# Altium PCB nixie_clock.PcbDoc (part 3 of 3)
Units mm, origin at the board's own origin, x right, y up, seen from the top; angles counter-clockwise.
Board outline 295 x 120 mm, 2 copper layers (Top Layer, Bottom Layer), stack 0.325 mm thick; 320 components, 396 nets, 1330 pads, 452 vias.
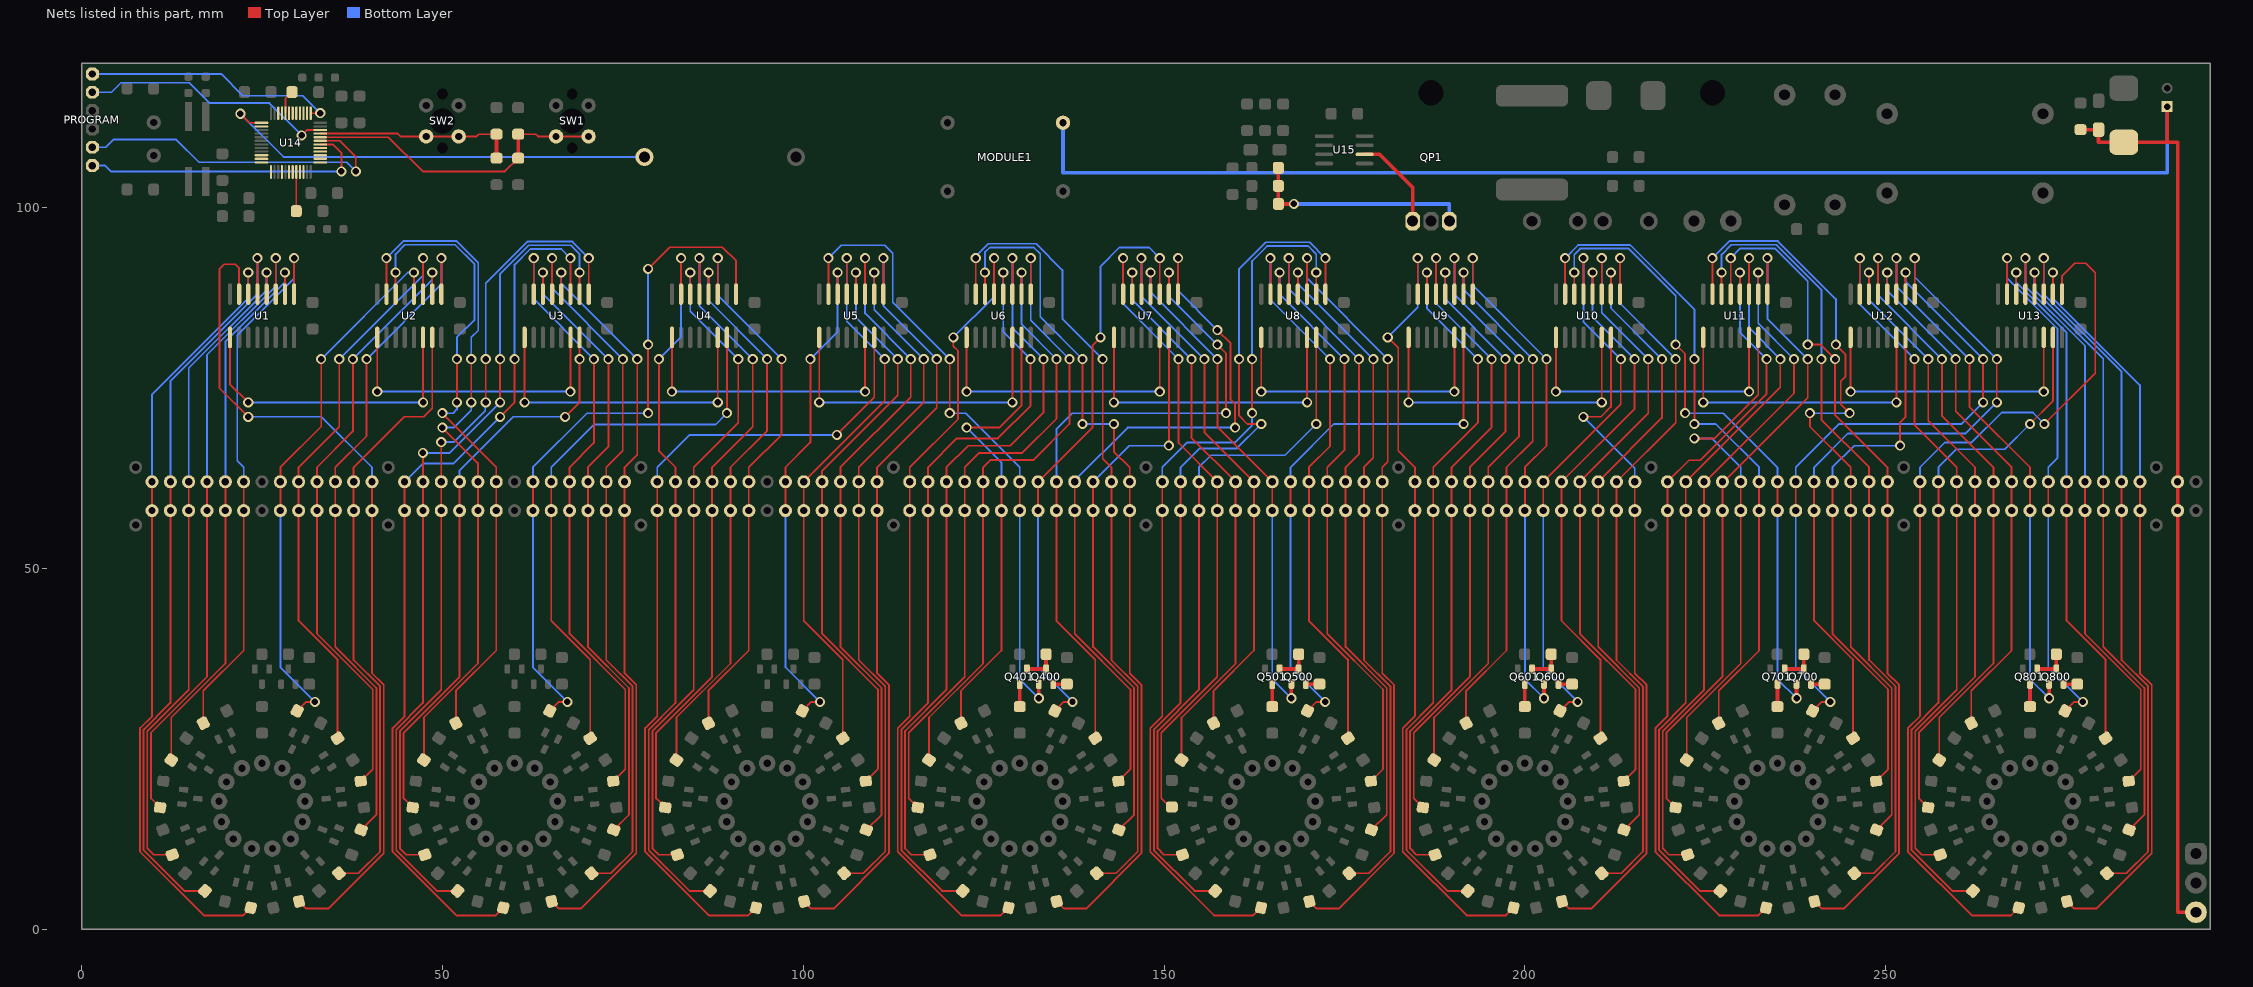
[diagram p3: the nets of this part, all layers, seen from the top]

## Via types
v1: diameter 1.397, hole 0.889, Top Layer to Bottom Layer, 452 vias

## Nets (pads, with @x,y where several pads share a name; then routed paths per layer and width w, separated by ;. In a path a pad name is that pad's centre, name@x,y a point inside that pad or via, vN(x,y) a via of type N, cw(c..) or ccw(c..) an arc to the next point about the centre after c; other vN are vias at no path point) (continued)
NetQ400_1: pad.400 Q400.1 U5.7 | length 88.4
  Top Layer w0.254: U5.7@103.492,88 v1(103.492,93) ; v1(120.3,71.5) v1(120.3,79) ; pad.400@130,58 pad.400@130,62
  Top Layer w0.508: v1(132.65,32) Q400.1@132.65,33.95
  Bottom Layer w0.254: v1(103.492,93) 105.262,94.77 111.31,94.77 112.4,93.68 112.4,86.9 v1(120.3,79) ; v1(120.3,71.5) 122.5,71.5 130,64 pad.400@130,62 ; pad.400@130,58 130,34.65 v1(132.65,32)
NetQ400_2: Q400.2 R400.1 | length 1.9
  Top Layer w0.508: Q400.2@134.65,33.95 R400.1@136.55,33.954
NetQ400_3: Q400.3 Q401.1 R402.2 | length 4.7
  Top Layer w0.508: Q401.1@131,36.05 Q400.3@133.65,36.05 R402.2@133.652,38.1
NetQ401_3: Q401.3 R401.1 | length 3.1
  Top Layer w0.508: R401.1@130,30.842 Q401.3@130,33.95
NetQ500_1: pad.500 Q500.1 U7.4 | length 72
  Top Layer w0.254: U7.4@148.135,88 v1(148.135,91) ; v1(157.4,79) 157.4,69.6 pad.500@165,62 pad.500@165,58
  Top Layer w0.508: v1(167.65,32) Q500.1@167.65,33.95
  Bottom Layer w0.254: v1(148.135,91) 148.135,88.265 v1(157.4,79) ; pad.500@165,58 165,34.65 v1(167.65,32)
NetQ500_2: Q500.2 R500.1 | length 1.9
  Top Layer w0.508: Q500.2@169.65,33.95 R500.1@171.55,33.954
NetQ500_3: Q500.3 Q501.1 R502.2 | length 4.7
  Top Layer w0.508: Q501.1@166,36.05 Q500.3@168.65,36.05 R502.2@168.651,38.1
NetQ501_3: Q501.3 R501.1 | length 3.1
  Top Layer w0.508: R501.1@165,30.842 Q501.3@165,33.95
NetQ600_1: pad.600 Q600.1 U9.1 | length 74.5
  Top Layer w0.254: U9.1@192.778,88 v1(192.778,93) ; pad.600@200,58 pad.600@200,62 200,64 203,67 v1(203,79)
  Top Layer w0.508: v1(202.65,32) Q600.1@202.65,33.95
  Bottom Layer w0.254: v1(192.778,93) 192.778,89.222 v1(203,79) ; pad.600@200,58 200,34.65 v1(202.65,32)
NetQ600_2: Q600.2 R600.1 | length 1.9
  Top Layer w0.508: Q600.2@204.65,33.95 R600.1@206.55,33.954
NetQ600_3: Q600.3 Q601.1 R602.2 | length 4.7
  Top Layer w0.508: Q601.1@201,36.05 Q600.3@203.65,36.05 R602.2@203.652,38.1
NetQ601_3: Q601.3 R601.1 | length 3.1
  Top Layer w0.508: R601.1@200,30.842 Q601.3@200,33.95
NetQ700_1: pad.700 Q700.1 U10.6 | length 90.4
  Top Layer w0.254: U10.6@206.845,88 v1(206.845,91) ; v1(220.9,81) 222.2,79.7 v1(222.2,71.5) ; pad.700@235,58 pad.700@235,62
  Top Layer w0.508: v1(237.65,32) Q700.1@237.65,33.95
  Bottom Layer w0.254: v1(206.845,91) 206.845,93.485 207.66,94.3 214.382,94.3 220.9,87.782 v1(220.9,81) ; v1(222.2,71.5) 227.5,71.5 235,64 pad.700@235,62 ; pad.700@235,58 235,34.65 v1(237.65,32)
NetQ700_2: Q700.2 R700.1 | length 1.9
  Top Layer w0.508: Q700.2@239.65,33.95 R700.1@241.55,33.954
NetQ700_3: Q700.3 Q701.1 R702.2 | length 4.7
  Top Layer w0.508: Q701.1@236,36.05 Q700.3@238.65,36.05 R702.2@238.651,38.1
NetQ701_3: Q701.3 R701.1 | length 3.1
  Top Layer w0.508: R701.1@235,30.842 Q701.3@235,33.95
NetQ800_1: pad.800 Q800.1 U12.3 | length 76.7
  Top Layer w0.254: U12.3@251.488,88 v1(251.488,93) ; v1(261.6,79) 261.6,72.4 270,64 pad.800@270,62 pad.800@270,58
  Top Layer w0.508: v1(272.65,32) Q800.1@272.65,33.95
  Bottom Layer w0.254: v1(251.488,93) 251.488,89.112 v1(261.6,79) ; pad.800@270,58 270,34.65 v1(272.65,32)
NetQ800_2: Q800.2 R800.1 | length 1.9
  Top Layer w0.508: Q800.2@274.65,33.95 R800.1@276.55,33.954
NetQ800_3: Q800.3 Q801.1 R802.2 | length 4.7
  Top Layer w0.508: Q801.1@271,36.05 Q800.3@273.65,36.05 R802.2@273.651,38.1
NetQ801_3: Q801.3 R801.1 | length 3.1
  Top Layer w0.508: R801.1@270,30.842 Q801.3@270,33.95
NetQP1_1: QP1.1 U15.6 | length 14.2
  Top Layer w0.508: U15.6@177.8,107.365 179.885,107.365 184.46,102.79 QP1.1@184.46,98.11 QP1.1@184.46,97.11
NetQP1_3: QP1.3 RP8.2 RP10.1 RP11.1 | length 31.1
  Top Layer w0.508: RP8.2@165.842,105.5 RP10.1@165.842,103 RP11.1@165.842,100.5 v1(168,100.5)
  Bottom Layer w0.508: v1(168,100.5) 189.54,100.5 QP1.3@189.54,98.11
NetR1_2: pad.1 R1.2 U1.1 | length 75.4
  Top Layer w0.254: R1.2@16.863,28.541 16.863,33.022 22.46,38.618 pad.1@22.46,58 pad.1@22.46,62 ; U1.1@29.445,88 v1(29.445,93)
  Bottom Layer w0.254: pad.1@22.46,62 22.46,64 21.56,64.9 21.56,82.33 29.445,90.215 v1(29.445,93)
NetR2_2: pad.2 R2.2 U1.2 | length 77.1
  Top Layer w0.254: R2.2@12.432,23.438 12.432,29.327 19.92,36.815 pad.2@19.92,58 pad.2@19.92,62 ; U1.2@28.175,88 v1(28.175,91)
  Bottom Layer w0.254: pad.2@19.92,62 19.92,81.408 28.175,89.663 v1(28.175,91)
NetR3_2: pad.3 R3.2 U1.3 | length 88.8
  Top Layer w0.254: R3.2@10.88,16.86 9.614,18.126 9.614,27.227 17.38,34.993 pad.3@17.38,58 pad.3@17.38,62 ; U1.3@26.905,88 v1(26.905,93)
  Bottom Layer w0.254: pad.3@17.38,62 17.38,79.587 26.905,89.112 v1(26.905,93)
NetR4_2: pad.4 R4.2 U1.4 | length 93.5
  Top Layer w0.254: R4.2@12.563,10.314 9.976,10.314 9.106,11.184 9.106,27.438 14.84,33.172 pad.4@14.84,58 pad.4@14.84,62 ; U1.4@25.635,88 v1(25.635,91)
  Bottom Layer w0.254: pad.4@14.84,62 14.84,77.765 25.635,88.56 v1(25.635,91)
NetR5_2: pad.5 R5.2 U1.5 | length 104.4
  Top Layer w0.254: pad.5@12.3,62 pad.5@12.3,58 12.3,31.35 8.598,27.648 8.598,10.94 14.239,5.3 R5.2@17.094,5.3 ; U1.5@24.365,88 v1(24.365,93)
  Bottom Layer w0.254: pad.5@12.3,62 12.3,75.944 24.365,88.009 v1(24.365,93)
NetR6_2: pad.6 R6.2 U1.6 | length 108.9
  Top Layer w0.254: pad.6@9.76,62 pad.6@9.76,58 9.76,29.528 8.09,27.858 8.09,10.73 16.92,1.9 22.371,1.9 R6.2@23.437,2.966 ; U1.6@23.095,88 v1(23.095,91)
  Bottom Layer w0.254: pad.6@9.769,62 9.769,74.131 23.095,87.457 v1(23.095,91)
NetR7_2: pad.7 R7.2 U1.7 | length 118.4
  Top Layer w0.254: U1.7@21.825,88 21.825,91.575 21.27,92.13 19.79,92.13 19.1,91.44 19.1,74.995 v1(23.095,71) ; R7.2@30.138,3.847 31.135,2.85 34.2,2.85 41.87,10.52 41.87,33.844 40.24,35.474 pad.7@40.24,58 pad.7@40.24,62
  Bottom Layer w0.254: v1(23.095,71) 33.24,71 40.24,64 pad.7@40.24,62
NetR8_2: pad.8 R8.2 U2.15 | length 85.8
  Top Layer w0.254: R8.2@35.662,7.742 38.342,7.742 41.362,10.762 41.362,33.633 37.7,37.295 pad.8@37.7,58 pad.8@37.7,62 37.7,64 44.7,71 47.402,71 48.592,72.19 U2.15@48.592,82
NetR9_2: pad.9 R9.2 U2.1 | length 93.6
  Top Layer w0.254: R9.2@38.743,13.757 40.854,15.868 40.854,33.423 35.16,39.117 pad.9@35.16,58 pad.9@35.16,62 35.16,64 39.5,68.34 v1(39.5,79) ; U2.1@49.862,88 v1(49.862,93)
  Bottom Layer w0.254: v1(39.5,79) 49.862,89.362 v1(49.862,93)
NetR10_2: pad.10 R10.2 U2.2 | length 84
  Top Layer w0.254: v1(37.6,79) 37.6,68.98 32.62,64 pad.10@32.62,62 pad.10@32.62,58 32.62,40.938 40.346,33.212 40.346,22.185 R10.2@38.676,20.515 ; U2.2@48.592,88 v1(48.592,91)
  Bottom Layer w0.254: v1(37.6,79) 48.592,89.992 v1(48.592,91)
NetR11_2: pad.11 R11.2 U2.3 | length 80.9
  Top Layer w0.254: R11.2@35.476,26.468 35.476,37.364 30.08,42.76 pad.11@30.08,58 pad.11@30.08,62 30.08,64 35.7,69.62 v1(35.7,79) ; U2.3@47.322,88 v1(47.322,93)
  Bottom Layer w0.254: v1(35.7,79) 47.322,90.622 v1(47.322,93)
NetR12_2: pad.12 R12.2 U2.4 | length 75.6
  Top Layer w0.254: pad.12@27.54,58 pad.12@27.54,62 27.54,64 33.2,69.66 v1(33.2,79) ; R12.2@29.876,30.252 31.125,31.5 v1(32.32,31.5) ; U2.4@46.052,88 v1(46.052,91)
  Bottom Layer w0.254: pad.12@27.54,58 27.54,36.28 v1(32.32,31.5) ; v1(33.2,79) 45.2,91 v1(46.052,91)
NetR13_2: pad.13 R13.2 U2.6 | length 89.8
  Top Layer w0.254: U2.6@43.512,88 v1(43.512,91) ; v1(50,71.5) 57.46,64.04 pad.13@57.46,62 pad.13@57.46,58 57.46,38.618 51.863,33.022 R13.2@51.863,28.541 ; v1(52,73) v1(52,79)
  Bottom Layer w0.254: v1(43.512,91) 43.512,93.552 44.792,94.832 51.746,94.832 54.452,92.126 54.452,84.452 52,82 v1(52,79) ; v1(50,71.5) 51.48,71.5 52,72.02 v1(52,73)
NetR14_2: pad.14 R14.2 U2.7 | length 97
  Top Layer w0.254: U2.7@42.242,88 v1(42.242,93) ; R14.2@47.432,23.438 47.432,29.327 54.92,36.815 pad.14@54.92,58 pad.14@54.92,62 54.92,64.58 v1(50,69.5) ; v1(54,73) v1(54,79)
  Bottom Layer w0.254: v1(42.242,93) 44.582,95.34 51.957,95.34 54.96,92.337 54.96,82.96 54,82 v1(54,79) ; v1(50,69.5) 51.59,69.5 54,71.91 v1(54,73)
NetR15_2: pad.15 R15.2 U3.15 | length 80
  Top Layer w0.254: R15.2@45.88,16.86 44.614,18.126 44.614,27.227 52.38,34.993 pad.15@52.38,58 pad.15@52.38,62 ; v1(67,71) 69.008,73.008 v1(69.008,79) U3.15@69.008,82
  Bottom Layer w0.254: pad.15@52.38,62 52.38,63.58 59.8,71 v1(67,71)
NetR16_2: pad.16 R16.2 U3.1 | length 110.7
  Top Layer w0.254: R16.2@47.563,10.314 44.976,10.314 44.106,11.184 44.106,27.438 49.84,33.172 pad.16@49.84,58 pad.16@49.84,62 v1(49.84,67.5) ; v1(56,73) v1(56,79) ; U3.1@70.278,88 v1(70.278,93)
  Bottom Layer w0.254: v1(49.84,67.5) 51.6,67.5 55.93,71.83 55.93,72.93 v1(56,73) ; v1(56,79) 56,89.52 61.75,95.27 68.008,95.27 v1(70.278,93)
NetR17_2: pad.17 R17.2 U3.2 | length 117.5
  Top Layer w0.254: v1(47.3,66) pad.17@47.3,62 pad.17@47.3,58 47.3,31.35 43.598,27.648 43.598,10.94 49.239,5.3 R17.2@52.094,5.3 ; v1(58,73) v1(58,79) ; U3.2@69.008,88 v1(69.008,91)
  Bottom Layer w0.254: v1(47.3,66) 51,66 v1(58,73) ; v1(58,79) 58,90.802 61.96,94.762 67.798,94.762 69.008,93.552 v1(69.008,91)
NetR18_2: pad.18 R18.2 U3.3 | length 124.4
  Top Layer w0.254: pad.18@44.76,62 pad.18@44.76,58 44.76,29.528 43.09,27.858 43.09,10.73 51.92,1.9 57.371,1.9 R18.2@58.437,2.966 ; v1(58,71) 60,73 v1(60,79) ; U3.3@67.738,88 v1(67.738,93)
  Bottom Layer w0.254: pad.18@44.76,62 47.28,64.52 51.52,64.52 v1(58,71) ; v1(60,79) 60,92.083 62.171,94.254 66.484,94.254 v1(67.738,93)
NetR19_2: pad.19 R19.2 U3.4 | length 104.6
  Top Layer w0.254: R19.2@65.138,3.847 66.135,2.85 69.2,2.85 76.87,10.52 76.87,33.844 75.24,35.474 pad.19@75.24,58 pad.19@75.24,62 75.24,64 77,65.76 v1(77,79) ; U3.4@66.468,88 v1(66.468,91)
  Bottom Layer w0.254: v1(66.468,91) 66.468,89.532 v1(77,79)
NetR20_2: pad.20 R20.2 U3.5 | length 100.7
  Top Layer w0.254: U3.5@65.198,88 v1(65.198,93) ; R20.2@70.662,7.742 73.342,7.742 76.362,10.762 76.362,33.633 72.7,37.295 pad.20@72.7,58 pad.20@72.7,62 72.7,64 75,66.3 v1(75,79)
  Bottom Layer w0.254: v1(65.198,93) 65.198,88.802 v1(75,79)
NetR21_2: pad.21 R21.2 U3.6 | length 88.4
  Top Layer w0.254: U3.6@63.928,88 v1(63.928,91) ; v1(73,79) 73,66.84 70.16,64 pad.21@70.16,62 pad.21@70.16,58 70.16,39.117 75.854,33.423 75.854,15.868 R21.2@73.743,13.757
  Bottom Layer w0.254: v1(63.928,91) 63.928,88.072 v1(73,79)
NetR22_2: pad.22 R22.2 U3.7 | length 86.2
  Top Layer w0.254: U3.7@62.658,88 v1(62.658,93) ; v1(71,79) 71,67.38 67.62,64 pad.22@67.62,62 pad.22@67.62,58 67.62,40.938 75.346,33.212 75.346,22.185 R22.2@73.676,20.515
  Bottom Layer w0.254: v1(62.658,93) 62.658,87.342 v1(71,79)
NetR23_2: pad.23 R23.2 U4.15 | length 77.7
  Top Layer w0.254: pad.23@65.08,62 pad.23@65.08,58 65.08,42.76 70.476,37.364 R23.2@70.476,26.468 ; v1(89.425,71.5) U4.15@89.425,82
  Bottom Layer w0.254: pad.23@65.08,62 65.08,64 71.001,69.921 87.846,69.921 v1(89.425,71.5)
NetR24_2: pad.24 R24.2 U4.1 | length 95.3
  Top Layer w0.254: pad.24@62.54,58 pad.24@62.54,62 ; R24.2@64.876,30.252 66.125,31.5 v1(67.32,31.5) ; v1(78.5,71.5) v1(78.5,81) ; v1(78.5,91.5) 81.5,94.5 88.8,94.5 90.695,92.605 U4.1@90.695,88
  Bottom Layer w0.254: pad.24@62.54,58 62.54,36.28 v1(67.32,31.5) ; pad.24@62.54,62 62.54,64 70.04,71.5 v1(78.5,71.5) ; v1(78.5,81) v1(78.5,91.5)
NetR25_2: pad.25 R25.2 U4.3 | length 77.3
  Top Layer w0.254: R25.2@86.863,28.541 86.863,33.022 92.46,38.618 pad.25@92.46,58 pad.25@92.46,62 92.46,64 97,68.54 v1(97,79) ; U4.3@88.155,88 v1(88.155,93)
  Bottom Layer w0.254: v1(88.155,93) 88.155,87.845 v1(97,79)
NetR26_2: pad.26 R26.2 U4.4 | length 79.1
  Top Layer w0.254: R26.2@82.432,23.438 82.432,29.327 89.92,36.815 pad.26@89.92,58 pad.26@89.92,62 89.92,64 95,69.08 v1(95,79) ; U4.4@86.885,88 v1(86.885,91)
  Bottom Layer w0.254: v1(86.885,91) 86.885,87.115 v1(95,79)
NetR27_2: pad.27 R27.2 U4.5 | length 90.3
  Top Layer w0.254: R27.2@80.88,16.86 79.614,18.126 79.614,27.227 87.38,34.993 pad.27@87.38,58 pad.27@87.38,62 87.38,64 93,69.62 v1(93,79) ; U4.5@85.615,88 v1(85.615,93)
  Bottom Layer w0.254: v1(85.615,93) 85.615,86.385 v1(93,79)
NetR28_2: pad.28 R28.2 U4.6 | length 94.3
  Top Layer w0.254: R28.2@82.563,10.314 79.976,10.314 79.106,11.184 79.106,27.438 84.84,33.172 pad.28@84.84,58 pad.28@84.84,62 84.84,64 91,70.16 v1(91,79) ; U4.6@84.345,88 v1(84.345,91)
  Bottom Layer w0.254: v1(84.345,91) 84.345,85.655 v1(91,79)
NetR29_2: pad.29 R29.2 U4.7 | length 101.7
  Top Layer w0.254: v1(80,79) 80,66.3 82.3,64 pad.29@82.3,62 pad.29@82.3,58 82.3,31.35 78.598,27.648 78.598,10.94 84.239,5.3 R29.2@87.094,5.3 ; U4.7@83.075,88 v1(83.075,93)
  Bottom Layer w0.254: v1(80,79) 83.075,82.075 v1(83.075,93)
NetR30_2: pad.30 R30.2 U5.15 | length 115.8
  Top Layer w0.254: pad.30@79.76,62 pad.30@79.76,58 79.76,29.528 78.09,27.858 78.09,10.73 86.92,1.9 92.371,1.9 R30.2@93.437,2.966 ; v1(104.66,68.5) 109.842,73.682 U5.15@109.842,82
  Bottom Layer w0.254: pad.30@79.76,62 79.76,64 84.26,68.5 v1(104.66,68.5)
NetR31_2: pad.31 R31.2 U5.1 | length 110
  Top Layer w0.254: R31.2@100.138,3.847 101.135,2.85 104.2,2.85 111.87,10.52 111.87,33.844 110.24,35.474 pad.31@110.24,58 pad.31@110.24,62 110.24,64 118.5,72.26 v1(118.5,79) ; U5.1@111.112,88 v1(111.112,93)
  Bottom Layer w0.254: v1(111.112,93) 111.112,86.388 v1(118.5,79)
NetR32_2: pad.32 R32.2 U5.2 | length 98.3
  Top Layer w0.254: R32.2@105.662,7.742 108.342,7.742 111.362,10.762 111.362,33.633 107.7,37.295 pad.32@107.7,58 pad.32@107.7,62 107.7,64 116.7,73 v1(116.7,79) ; U5.2@109.842,88 v1(109.842,91)
  Bottom Layer w0.254: v1(109.842,91) 109.842,85.858 v1(116.7,79)
NetR33_2: pad.33 R33.2 U5.3 | length 94.1
  Top Layer w0.254: U5.3@108.572,88 v1(108.572,93) ; R33.2@108.743,13.757 110.854,15.868 110.854,33.423 105.16,39.117 pad.33@105.16,58 pad.33@105.16,62 105.16,64 114.9,73.74 v1(114.9,79)
  Bottom Layer w0.254: v1(108.572,93) 108.572,85.328 v1(114.9,79)
NetR34_2: pad.34 R34.2 U5.4 | length 84.1
  Top Layer w0.254: U5.4@107.302,88 v1(107.302,91) ; R34.2@108.676,20.515 110.346,22.185 110.346,33.212 102.62,40.938 pad.34@102.62,58 pad.34@102.62,62 102.62,63.5 113.1,73.98 v1(113.1,79)
  Bottom Layer w0.254: v1(107.302,91) 107.302,84.798 v1(113.1,79)
NetR35_2: pad.35 R35.2 U5.5 | length 80.6
  Top Layer w0.254: R35.2@105.476,26.468 105.476,37.364 100.08,42.76 pad.35@100.08,58 pad.35@100.08,62 111.3,73.22 v1(111.3,79) ; U5.5@106.032,88 v1(106.032,93)
  Bottom Layer w0.254: v1(106.032,93) 106.032,84.268 v1(111.3,79)
NetR36_2: pad.36 R36.2 U5.6 | length 70.4
  Top Layer w0.254: pad.36@97.54,58 pad.36@97.54,62 97.54,64 101,67.46 v1(101,79) ; R36.2@99.876,30.252 101.125,31.5 v1(102.32,31.5) ; U5.6@104.762,88 v1(104.762,91)
  Bottom Layer w0.254: pad.36@97.54,58 97.54,36.28 v1(102.32,31.5) ; v1(101,79) 104.762,82.762 v1(104.762,91)
NetR37_2: pad.37 R37.2 U6.15 | length 63.6
  Top Layer w0.254: R37.2@121.863,28.541 121.863,33.022 127.46,38.618 pad.37@127.46,58 pad.37@127.46,62 ; v1(122.638,69.5) 127.17,69.5 130.258,72.588 U6.15@130.258,82
  Bottom Layer w0.254: v1(122.638,69.5) 127.46,64.678 pad.37@127.46,62
NetR38_2: pad.38 R38.2 U6.1 | length 88.3
  Top Layer w0.254: R38.2@117.432,23.438 117.432,29.327 124.92,36.815 pad.38@124.92,58 pad.38@124.92,62 124.92,64 125.92,65 131.88,65 136.9,70.02 v1(136.9,79) ; U6.1@131.528,88 v1(131.528,93)
  Bottom Layer w0.254: v1(131.528,93) 131.528,84.372 v1(136.9,79)
NetR39_2: pad.39 R39.2 U6.2 | length 91.7
  Top Layer w0.254: R39.2@115.88,16.86 114.614,18.126 114.614,27.227 122.38,34.993 pad.39@122.38,58 pad.39@122.38,62 122.38,64 124.38,66 130.35,66 135.1,70.75 v1(135.1,79) ; U6.2@130.258,88 v1(130.258,91)
  Bottom Layer w0.254: v1(130.258,91) 130.258,83.842 v1(135.1,79)
NetR40_2: pad.40 R40.2 U6.3 | length 103.8
  Top Layer w0.254: R40.2@117.563,10.314 114.976,10.314 114.106,11.184 114.106,27.438 119.84,33.172 pad.40@119.84,58 pad.40@119.84,62 119.84,64 122.84,67 128.69,67 133.3,71.61 v1(133.3,79) ; U6.3@128.988,88 v1(128.988,93)
  Bottom Layer w0.254: v1(128.988,93) 128.988,83.312 v1(133.3,79)
NetR41_2: pad.41 R41.2 U6.4 | length 106.2
  Top Layer w0.254: R41.2@122.094,5.3 119.239,5.3 113.598,10.94 113.598,27.648 117.3,31.35 pad.41@117.3,58 pad.41@117.3,62 117.3,64 121.3,68 126.98,68 131.5,72.52 v1(131.5,79) ; U6.4@127.718,88 v1(127.718,91)
  Bottom Layer w0.254: v1(127.718,91) 127.718,82.782 v1(131.5,79)
NetR42_2: pad.42 R42.2 U6.5 | length 112.8
  Top Layer w0.254: v1(120.8,82) 120.8,80.79 121.45,80.14 121.45,70.69 114.76,64 pad.42@114.76,62 pad.42@114.76,58 114.76,29.528 113.09,27.858 113.09,10.73 121.92,1.9 127.371,1.9 R42.2@128.437,2.966 ; U6.5@126.448,88 v1(126.448,93)
  Bottom Layer w0.254: v1(120.8,82) 126.448,87.648 v1(126.448,93)
NetR43_2: pad.43 R43.2 U6.6 | length 120.8
  Top Layer w0.254: U6.6@125.178,88 v1(125.178,91) ; R43.2@135.138,3.847 136.135,2.85 139.2,2.85 146.87,10.52 146.87,33.844 145.24,35.474 pad.43@145.24,58 pad.43@145.24,62 145.24,64 143.055,66.185 v1(143.055,70) ; v1(138.7,70) v1(138.7,79)
  Bottom Layer w0.254: v1(125.178,91) 125.178,93.788 125.852,94.462 131.968,94.462 132.84,93.59 132.84,84.86 v1(138.7,79) ; v1(138.7,70) v1(143.055,70)
NetR44_2: pad.44 R44.2 U6.7 | length 111.3
  Top Layer w0.254: U6.7@123.908,88 v1(123.908,93) ; R44.2@140.662,7.742 143.342,7.742 146.362,10.762 146.362,33.633 142.7,37.295 pad.44@142.7,58 pad.44@142.7,62 142.7,64 141.5,65.2 v1(141.5,79)
  Bottom Layer w0.254: v1(123.908,93) 123.908,93.237 125.642,94.97 132.27,94.97 135.91,91.33 135.91,84.59 v1(141.5,79)
NetR45_2: pad.45 R45.2 U7.15 | length 79.1
  Top Layer w0.254: pad.45@140.16,62 pad.45@140.16,58 140.16,39.117 145.854,33.423 145.854,15.868 R45.2@143.743,13.757 ; v1(150.675,67) 150.675,70.515 U7.15@150.675,82
  Bottom Layer w0.254: pad.45@140.16,62 145.16,67 v1(150.675,67)
NetR46_2: pad.46 R46.2 U7.1 | length 102.6
  Top Layer w0.254: pad.46@137.62,62 pad.46@137.62,58 137.62,40.938 145.346,33.212 145.346,22.185 R46.2@143.676,20.515 ; U7.1@151.945,88 v1(151.945,93) ; v1(157.4,83) 159.22,81.18 159.22,73.39 159.84,72.77 v1(159.84,69.5)
  Bottom Layer w0.254: pad.46@137.62,62 137.62,62.178 144.942,69.5 v1(159.84,69.5) ; v1(151.945,93) 151.945,88.455 v1(157.4,83)
NetR47_2: pad.47 R47.2 U7.2 | length 95.3
  Top Layer w0.254: pad.47@135.08,62 pad.47@135.08,58 135.08,42.76 140.476,37.364 R47.2@140.476,26.468 ; U7.2@150.675,88 v1(150.675,91) ; v1(157.4,81) 158.59,79.81 v1(158.59,71.5)
  Bottom Layer w0.254: pad.47@135.08,62 135.08,69.29 137.29,71.5 v1(158.59,71.5) ; v1(150.675,91) 150.675,87.725 v1(157.4,81)
NetR48_2: pad.48 R48.2 U7.3 | length 83.8
  Top Layer w0.254: pad.48@132.54,58 pad.48@132.54,62 140.1,69.56 140.1,80.9 v1(141.2,82) ; R48.2@134.876,30.252 136.125,31.5 v1(137.32,31.5) ; U7.3@149.405,88 v1(149.405,93)
  Bottom Layer w0.254: pad.48@132.54,58 132.54,36.28 v1(137.32,31.5) ; v1(141.2,82) 141.2,91.84 143.82,94.46 147.945,94.46 v1(149.405,93)
NetR49_2: pad.49 R49.2 U7.5 | length 78.2
  Top Layer w0.254: U7.5@146.865,88 v1(146.865,93) ; v1(155.6,79) 155.6,68.86 pad.49@162.46,62 pad.49@162.46,58 162.46,38.618 156.863,33.022 R49.2@156.863,28.541
  Bottom Layer w0.254: v1(146.865,93) 146.865,87.735 v1(155.6,79)
NetR50_2: pad.50 R50.2 U7.6 | length 79.6
  Top Layer w0.254: U7.6@145.595,88 v1(145.595,91) ; R50.2@152.432,23.438 152.432,29.327 159.92,36.815 pad.50@159.92,58 pad.50@159.92,62 153.8,68.12 v1(153.8,79)
  Bottom Layer w0.254: v1(145.595,91) 145.595,87.205 v1(153.8,79)
NetR51_2: pad.51 R51.2 U7.7 | length 90.3
  Top Layer w0.254: U7.7@144.325,88 v1(144.325,93) ; R51.2@150.88,16.86 149.614,18.126 149.614,27.227 157.38,34.993 pad.51@157.38,58 pad.51@157.38,62 152,67.38 v1(152,79)
  Bottom Layer w0.254: v1(144.325,93) 144.325,86.675 v1(152,79)
NetR52_2: pad.52 R52.2 U8.15 | length 89.7
  Top Layer w0.254: R52.2@152.563,10.314 149.976,10.314 149.106,11.184 149.106,27.438 154.84,33.172 pad.52@154.84,58 pad.52@154.84,62 ; v1(171.092,70) U8.15@171.092,82
  Bottom Layer w0.254: pad.52@154.84,62 154.84,64 156.51,65.67 166.762,65.67 v1(171.092,70)
NetR53_2: pad.53 R53.2 U8.1 | length 122.4
  Top Layer w0.254: pad.53@152.3,62 pad.53@152.3,58 152.3,31.35 148.598,27.648 148.598,10.94 154.239,5.3 R53.2@157.094,5.3 ; v1(160.4,79) 160.4,71.16 161.56,70 v1(163.472,70) ; U8.1@172.362,88 v1(172.362,93)
  Bottom Layer w0.254: pad.53@152.3,62 152.3,64 154.93,66.63 160.102,66.63 v1(163.472,70) ; v1(160.4,79) 160.4,91.51 164.07,95.18 170.182,95.18 v1(172.362,93)
NetR54_2: pad.54 R54.2 U8.2 | length 127.4
  Top Layer w0.254: pad.54@149.76,62 pad.54@149.76,58 149.76,29.528 148.09,27.858 148.09,10.73 156.92,1.9 162.371,1.9 R54.2@163.437,2.966 ; v1(162.2,71.5) v1(162.2,79) ; U8.2@171.092,88 v1(171.092,91)
  Bottom Layer w0.254: pad.54@149.76,58 pad.54@149.76,58.62 ; pad.54@149.76,62 149.76,64 153.22,67.46 159.86,67.46 162.2,69.8 v1(162.2,71.5) ; v1(162.2,79) 162.2,92.592 164.28,94.672 169.968,94.672 171.092,93.548 v1(171.092,91)
NetR55_2: pad.55 R55.2 U8.3 | length 108.4
  Top Layer w0.254: U8.3@169.822,88 v1(169.822,93) ; R55.2@170.138,3.847 171.135,2.85 174.2,2.85 181.87,10.52 181.87,33.844 180.24,35.474 pad.55@180.24,58 pad.55@180.24,62 180.24,64 181,64.76 v1(181,79)
  Bottom Layer w0.254: v1(169.822,93) 169.822,90.178 v1(181,79)
NetR56_2: pad.56 R56.2 U8.4 | length 96.6
  Top Layer w0.254: U8.4@168.552,88 v1(168.552,91) ; R56.2@175.662,7.742 178.342,7.742 181.362,10.762 181.362,33.633 177.7,37.295 pad.56@177.7,58 pad.56@177.7,62 177.7,64 179,65.3 v1(179,79)
  Bottom Layer w0.254: v1(168.552,91) 168.552,89.448 v1(179,79)
NetR57_2: pad.57 R57.2 U8.5 | length 92.3
  Top Layer w0.254: U8.5@167.282,88 v1(167.282,93) ; v1(177,79) 177,65.84 175.16,64 pad.57@175.16,62 pad.57@175.16,58 175.16,39.117 180.854,33.423 180.854,15.868 R57.2@178.743,13.757
  Bottom Layer w0.254: v1(167.282,93) 167.282,88.718 v1(177,79)
NetR58_2: pad.58 R58.2 U8.6 | length 82.1
  Top Layer w0.254: U8.6@166.012,88 v1(166.012,91) ; v1(175,79) 175,66.38 172.62,64 pad.58@172.62,62 pad.58@172.62,58 172.62,40.938 180.346,33.212 180.346,22.185 R58.2@178.676,20.515
  Bottom Layer w0.254: v1(166.012,91) 166.012,87.988 v1(175,79)
NetR59_2: pad.59 R59.2 U8.7 | length 78.4
  Top Layer w0.254: U8.7@164.742,88 v1(164.742,93) ; v1(173,79) 173,66.92 170.08,64 pad.59@170.08,62 pad.59@170.08,58 170.08,42.76 175.476,37.364 R59.2@175.476,26.468
  Bottom Layer w0.254: v1(164.742,93) 164.742,87.258 v1(173,79)
NetR60_2: pad.60 R60.2 U9.15 | length 75.9
  Top Layer w0.254: pad.60@167.54,58 pad.60@167.54,62 ; R60.2@169.876,30.252 171.125,31.5 v1(172.32,31.5) ; v1(191.508,70) U9.15@191.508,82
  Bottom Layer w0.254: pad.60@167.54,58 167.54,36.28 v1(172.32,31.5) ; pad.60@167.54,62 167.54,64 173.54,70 v1(191.508,70)
NetR61_2: pad.61 R61.2 U9.2 | length 73.3
  Top Layer w0.254: U9.2@191.508,88 v1(191.508,91) ; R61.2@191.863,28.541 191.863,33.022 197.46,38.618 pad.61@197.46,58 pad.61@197.46,62 197.46,64 201.1,67.64 v1(201.1,79)
  Bottom Layer w0.254: v1(191.508,91) 191.508,88.592 v1(201.1,79)
NetR62_2: pad.62 R62.2 U9.3 | length 83.1
  Top Layer w0.254: R62.2@187.432,23.438 187.432,29.327 194.92,36.815 pad.62@194.92,58 pad.62@194.92,62 194.92,64 199.2,68.28 v1(199.2,79) ; U9.3@190.238,88 v1(190.238,93)
  Bottom Layer w0.254: v1(190.238,93) 190.238,87.962 v1(199.2,79)
NetR63_2: pad.63 R63.2 U9.4 | length 86.4
  Top Layer w0.254: R63.2@185.88,16.86 184.614,18.126 184.614,27.227 192.38,34.993 pad.63@192.38,58 pad.63@192.38,62 192.38,64 197.3,68.92 v1(197.3,79) ; U9.4@188.968,88 v1(188.968,91)
  Bottom Layer w0.254: v1(188.968,91) 188.968,87.332 v1(197.3,79)
NetR64_2: pad.64 R64.2 U9.5 | length 98.5
  Top Layer w0.254: R64.2@187.563,10.314 184.976,10.314 184.106,11.184 184.106,27.438 189.84,33.172 pad.64@189.84,58 pad.64@189.84,62 189.84,64 195.4,69.56 v1(195.4,79) ; U9.5@187.698,88 v1(187.698,93)
  Bottom Layer w0.254: v1(187.698,93) 187.698,86.702 v1(195.4,79)
NetR65_2: pad.65 R65.2 U9.6 | length 100.9
  Top Layer w0.254: U9.6@186.428,88 v1(186.428,91) ; R65.2@192.094,5.3 189.239,5.3 183.598,10.94 183.598,27.648 187.3,31.35 pad.65@187.3,58 pad.65@187.3,62 187.3,64 193.5,70.2 v1(193.5,79)
  Bottom Layer w0.254: v1(186.428,91) 186.428,86.072 v1(193.5,79)
NetR66_2: pad.66 R66.2 U9.7 | length 110.7
  Top Layer w0.254: v1(181,82) 182.46,80.54 182.46,66.3 184.76,64 pad.66@184.76,62 pad.66@184.76,58 184.76,29.528 183.09,27.858 183.09,10.73 191.92,1.9 197.371,1.9 R66.2@198.437,2.966 ; U9.7@185.158,88 v1(185.158,93)
  Bottom Layer w0.254: v1(181,82) 185.158,86.158 v1(185.158,93)
NetR67_2: pad.67 R67.2 U10.15 | length 93.4
  Top Layer w0.254: R67.2@205.138,3.847 206.135,2.85 209.2,2.85 216.87,10.52 216.87,33.844 215.24,35.474 pad.67@215.24,58 pad.67@215.24,62 ; v1(208.115,71) 210.55,71 211.925,72.375 U10.15@211.925,82
  Bottom Layer w0.254: v1(208.115,71) 215.24,63.875 pad.67@215.24,62
NetR68_2: pad.68 R68.2 U10.1 | length 102.3
  Top Layer w0.254: R68.2@210.662,7.742 213.342,7.742 216.362,10.762 216.362,33.633 212.7,37.295 pad.68@212.7,58 pad.68@212.7,62 220.9,70.2 v1(220.9,79) ; U10.1@213.195,88 v1(213.195,93)
  Bottom Layer w0.254: v1(213.195,93) 213.195,86.705 v1(220.9,79)
NetR69_2: pad.69 R69.2 U10.2 | length 90.1
  Top Layer w0.254: U10.2@211.925,88 v1(211.925,91) ; R69.2@213.743,13.757 215.854,15.868 215.854,33.423 210.16,39.117 pad.69@210.16,58 pad.69@210.16,62 219,70.84 v1(219,79)
  Bottom Layer w0.254: v1(211.925,91) 211.925,86.075 v1(219,79)
NetR70_2: pad.70 R70.2 U10.3 | length 88
  Top Layer w0.254: U10.3@210.655,88 v1(210.655,93) ; R70.2@213.676,20.515 215.346,22.185 215.346,33.212 207.62,40.938 pad.70@207.62,58 pad.70@207.62,62 217.1,71.48 v1(217.1,79)
  Bottom Layer w0.254: v1(210.655,93) 210.655,85.445 v1(217.1,79)
NetR71_2: pad.71 R71.2 U10.4 | length 76.4
  Top Layer w0.254: U10.4@209.385,88 v1(209.385,91) ; R71.2@210.476,26.468 210.476,37.364 205.08,42.76 pad.71@205.08,58 pad.71@205.08,62 215.2,72.12 v1(215.2,79)
  Bottom Layer w0.254: v1(209.385,91) 209.385,84.815 v1(215.2,79)
NetR72_2: pad.72 R72.2 U10.5 | length 78
  Top Layer w0.254: pad.72@202.54,58 pad.72@202.54,62 213.3,72.76 v1(213.3,79) ; R72.2@204.876,30.252 206.125,31.5 v1(207.32,31.5) ; U10.5@208.115,88 v1(208.115,93)
  Bottom Layer w0.254: pad.72@202.54,58 202.54,36.28 v1(207.32,31.5) ; v1(208.115,93) 208.115,84.185 v1(213.3,79)
NetR73_2: pad.73 R73.2 U10.7 | length 92.5
  Top Layer w0.254: U10.7@205.575,88 v1(205.575,93) ; v1(223.5,70) v1(223.5,79) ; R73.2@226.863,28.541 226.863,33.022 232.46,38.618 pad.73@232.46,58 pad.73@232.46,62
  Bottom Layer w0.254: v1(205.575,93) 207.383,94.808 214.592,94.808 223.5,85.9 v1(223.5,79) ; v1(223.5,70) 226.46,70 232.46,64 pad.73@232.46,62
NetR74_2: pad.74 R74.2 U11.15 | length 71
  Top Layer w0.254: R74.2@222.432,23.438 222.432,29.327 229.92,36.815 pad.74@229.92,58 pad.74@229.92,62 ; v1(223.5,68) 226.3,68 232.342,74.042 U11.15@232.342,82
  Bottom Layer w0.254: v1(223.5,68) 225.92,68 229.92,64 pad.74@229.92,62
NetR75_2: pad.75 R75.2 U11.1 | length 92.2
  Top Layer w0.254: R75.2@220.88,16.86 219.614,18.126 219.614,27.227 227.38,34.993 pad.75@227.38,58 pad.75@227.38,62 227.558,62 239.158,73.6 239.2,73.6 v1(239.2,79) ; U11.1@233.612,88 v1(233.612,93)
  Bottom Layer w0.254: v1(233.612,93) 233.612,84.588 v1(239.2,79)
NetR76_2: pad.76 R76.2 U11.2 | length 96.3
  Top Layer w0.254: R76.2@222.563,10.314 219.976,10.314 219.106,11.184 219.106,27.438 224.84,33.172 pad.76@224.84,58 pad.76@224.84,62 225.018,62 237.3,74.282 v1(237.3,79) ; U11.2@232.342,88 v1(232.342,91)
  Bottom Layer w0.254: v1(232.342,91) 232.342,83.958 v1(237.3,79)
NetR77_2: pad.77 R77.2 U11.3 | length 106.6
  Top Layer w0.254: R77.2@227.094,5.3 224.239,5.3 218.598,10.94 218.598,27.648 222.3,31.35 pad.77@222.3,58 pad.77@222.3,62 235.4,75.1 v1(235.4,79) ; U11.3@231.072,88 v1(231.072,93)
  Bottom Layer w0.254: v1(231.072,93) 231.072,83.328 v1(235.4,79)
NetR78_2: pad.78 R78.2 U11.4 | length 111.5
  Top Layer w0.254: U11.4@229.802,88 v1(229.802,91) ; R78.2@233.437,2.966 232.371,1.9 226.92,1.9 218.09,10.73 218.09,27.858 219.76,29.528 pad.78@219.76,58 pad.78@219.76,62 222.75,64.99 224.3,64.99 233.5,74.19 v1(233.5,79)
  Bottom Layer w0.254: v1(229.802,91) 229.802,82.698 v1(233.5,79)
NetR79_2: pad.79 R79.2 U11.5 | length 119
  Top Layer w0.254: U11.5@228.532,88 v1(228.532,93) ; v1(239.2,81) 241,81 v1(243,79) 243,71.24 250.24,64 pad.79@250.24,62 pad.79@250.24,58 250.24,35.474 251.87,33.844 251.87,10.52 244.2,2.85 241.135,2.85 R79.2@240.138,3.847
  Bottom Layer w0.254: v1(228.532,93) 229.872,94.34 234.643,94.34 239.2,89.783 v1(239.2,81)
NetR80_2: pad.80 R80.2 U11.6 | length 111.5
  Top Layer w0.254: U11.6@227.262,88 v1(227.262,91) ; v1(241.1,79) 241.1,70.6 247.7,64 pad.80@247.7,62 pad.80@247.7,58 247.7,37.295 251.362,33.633 251.362,10.762 248.342,7.742 R80.2@245.662,7.742
  Bottom Layer w0.254: v1(227.262,91) 227.262,93.482 228.628,94.848 234.854,94.848 241.1,88.602 v1(241.1,79)
NetR81_2: pad.81 R81.2 U11.7 | length 112.4
  Top Layer w0.254: U11.7@225.992,88 v1(225.992,93) ; v1(239.5,71.5) 239.5,69.66 245.16,64 pad.81@245.16,62 pad.81@245.16,58 245.16,39.117 250.854,33.423 250.854,15.868 R81.2@248.743,13.757 ; v1(243.1,81) 244.42,79.68 244.42,76.57 243.77,75.92 243.77,72.73 v1(245,71.5)
  Bottom Layer w0.254: v1(225.992,93) 228.348,95.356 235.064,95.356 243.1,87.32 v1(243.1,81) ; v1(239.5,71.5) v1(245,71.5)
NetR82_2: pad.82 R82.2 U12.15 | length 73.3
  Top Layer w0.254: pad.82@242.62,62 pad.82@242.62,58 242.62,40.938 250.346,33.212 250.346,22.185 R82.2@248.676,20.515 ; v1(252,67) 252,70.23 252.758,70.988 U12.15@252.758,82
  Bottom Layer w0.254: pad.82@242.62,62 242.62,64 245.62,67 v1(252,67)
NetR83_2: pad.83 R83.2 U12.1 | length 98.5
  Top Layer w0.254: pad.83@240.08,62 pad.83@240.08,58 240.08,42.76 245.476,37.364 R83.2@245.476,26.468 ; U12.1@254.028,88 v1(254.028,93) ; v1(265.4,73) v1(265.4,79)
  Bottom Layer w0.254: pad.83@240.08,62 240.08,64 244.78,68.7 261.1,68.7 v1(265.4,73) ; v1(254.028,93) 254.028,90.372 v1(265.4,79)
NetR84_2: pad.84 R84.2 U12.2 | length 92.6
  Top Layer w0.254: pad.84@237.54,58 pad.84@237.54,62 ; R84.2@239.876,30.252 241.125,31.5 v1(242.32,31.5) ; U12.2@252.758,88 v1(252.758,91) ; v1(263.5,73) v1(263.5,79)
  Bottom Layer w0.254: pad.84@237.54,58 237.54,36.28 v1(242.32,31.5) ; pad.84@237.54,62 237.54,64 243.565,70.025 260.525,70.025 v1(263.5,73) ; v1(252.758,91) 252.758,89.742 v1(263.5,79)
NetR85_2: pad.85 R85.2 U12.4 | length 74.9
  Top Layer w0.254: U12.4@250.218,88 v1(250.218,91) ; v1(259.7,79) 259.7,71.76 267.46,64 pad.85@267.46,62 pad.85@267.46,58 267.46,38.618 261.863,33.022 R85.2@261.863,28.541
  Bottom Layer w0.254: v1(250.218,91) 250.218,88.482 v1(259.7,79)
NetR86_2: pad.86 R86.2 U12.5 | length 84.3
  Top Layer w0.254: U12.5@248.948,88 v1(248.948,93) ; R86.2@257.432,23.438 257.432,29.327 264.92,36.815 pad.86@264.92,58 pad.86@264.92,62 264.92,64 257.8,71.12 v1(257.8,79)
  Bottom Layer w0.254: v1(248.948,93) 248.948,87.852 v1(257.8,79)
NetR87_2: pad.87 R87.2 U12.6 | length 87
  Top Layer w0.254: U12.6@247.678,88 v1(247.678,91) ; R87.2@255.88,16.86 254.614,18.126 254.614,27.227 262.38,34.993 pad.87@262.38,58 pad.87@262.38,62 262.38,64 255.9,70.48 v1(255.9,79)
  Bottom Layer w0.254: v1(247.678,91) 247.678,87.222 v1(255.9,79)
NetR88_2: pad.88 R88.2 U12.7 | length 98.6
  Top Layer w0.254: U12.7@246.408,88 v1(246.408,93) ; v1(254,79) 254,69.84 259.84,64 pad.88@259.84,62 pad.88@259.84,58 259.84,33.172 254.106,27.438 254.106,11.184 254.976,10.314 R88.2@257.563,10.314
  Bottom Layer w0.254: v1(246.408,93) 246.408,86.592 v1(254,79)
NetR89_2: pad.89 R89.2 U13.15 | length 93.9
  Top Layer w0.254: pad.89@257.3,62 pad.89@257.3,58 257.3,31.35 253.598,27.648 253.598,10.94 259.239,5.3 R89.2@262.094,5.3 ; v1(270,70) 273.175,73.175 U13.15@273.175,82
  Bottom Layer w0.254: pad.89@257.3,62 257.3,64 259.81,66.51 266.51,66.51 v1(270,70)
NetR90_2: pad.90 R90.2 U13.1 | length 126.7
  Top Layer w0.254: pad.90@254.76,62 pad.90@254.76,58 254.76,29.528 253.09,27.858 253.09,10.73 261.92,1.9 267.371,1.9 R90.2@268.437,2.966 ; v1(272,70) 279.05,77.05 279.05,90.94 277.7,92.29 276.21,92.29 274.445,90.525 U13.1@274.445,88
  Bottom Layer w0.254: pad.90@254.76,62 254.76,64 258.22,67.46 261.94,67.46 266.08,71.6 270.4,71.6 v1(272,70)
NetR91_2: pad.91 R91.2 U13.2 | length 104.5
  Top Layer w0.254: U13.2@273.175,88 v1(273.175,91) ; R91.2@275.138,3.847 276.135,2.85 279.2,2.85 286.87,10.52 286.87,33.844 285.24,35.474 pad.91@285.24,58 pad.91@285.24,62
  Bottom Layer w0.254: v1(273.175,91) 273.175,87.457 285.24,75.392 pad.91@285.24,62
NetR92_2: pad.92 R92.2 U13.3 | length 100.2
  Top Layer w0.254: U13.3@271.905,88 v1(271.905,93) ; R92.2@280.662,7.742 283.342,7.742 286.362,10.762 286.362,33.633 282.7,37.295 pad.92@282.7,58 pad.92@282.7,62
  Bottom Layer w0.254: v1(271.905,93) 271.905,88.009 282.7,77.214 pad.92@282.7,62
NetR93_2: pad.93 R93.2 U13.4 | length 87.4
  Top Layer w0.254: U13.4@270.635,88 v1(270.635,91) ; pad.93@280.16,62 pad.93@280.16,58 280.16,39.117 285.854,33.423 285.854,15.868 R93.2@283.743,13.757
  Bottom Layer w0.254: v1(270.635,91) 270.635,88.56 280.16,79.035 pad.93@280.16,62
NetR94_2: pad.94 R94.2 U13.5 | length 84.8
  Top Layer w0.254: U13.5@269.365,88 v1(269.365,93) ; pad.94@277.62,62 pad.94@277.62,58 277.62,40.938 285.346,33.212 285.346,22.185 R94.2@283.676,20.515
  Bottom Layer w0.254: v1(269.365,93) 269.365,89.112 277.62,80.857 pad.94@277.62,62
NetR95_2: pad.95 R95.2 U13.6 | length 72.7
  Top Layer w0.254: U13.6@268.095,88 v1(268.095,91) ; pad.95@275.08,62 pad.95@275.08,58 275.08,42.76 280.476,37.364 R95.2@280.476,26.468
  Bottom Layer w0.254: v1(268.095,91) 268.095,89.663 275.08,82.678 pad.95@275.08,62
NetR96_2: pad.96 R96.2 U13.7 | length 74.9
  Top Layer w0.254: U13.7@266.825,88 v1(266.825,93) ; pad.96@272.54,58 pad.96@272.54,62 ; R96.2@274.876,30.252 276.125,31.5 v1(277.32,31.5)
  Bottom Layer w0.254: v1(266.825,93) 266.825,90.215 273.8,83.24 273.8,65.26 272.54,64 pad.96@272.54,62 ; pad.96@272.54,58 272.54,36.28 v1(277.32,31.5)
NetR109_2: R109.2 U14.44 | length 3.3
  Top Layer w0.254: U14.44@28.25,113.075 28.25,115.092 R109.2@29.158,116
NetR110_1: R110.1 U14.20 | length 5.4
  Top Layer w0.254: R110.1@29.749,99.5 29.75,99.502 U14.20@29.75,104.925
NetU1_9: U1.9 U2.14 | length 43.3
  Top Layer w0.254: U1.9@20.555,82 20.555,75.54 v1(23.095,73) ; v1(47.322,73) U2.14@47.322,82
  Bottom Layer w0.254: v1(23.095,73) v1(47.322,73)
NetU2_9: U2.9 U3.14 | length 41.8
  Top Layer w0.254: v1(40.972,74.5) U2.9@40.972,82 ; v1(67.738,74.5) U3.14@67.738,82
  Bottom Layer w0.254: v1(40.972,74.5) v1(67.738,74.5)
NetU3_9: U3.9 U4.14 | length 44.8
  Top Layer w0.254: v1(61.388,73) U3.9@61.388,82 ; v1(88.155,73) U4.14@88.155,82
  Bottom Layer w0.254: v1(61.388,73) v1(88.155,73)
NetU4_9: U4.9 U5.14 | length 41.8
  Top Layer w0.254: v1(81.805,74.5) U4.9@81.805,82 ; v1(108.572,74.5) U5.14@108.572,82
  Bottom Layer w0.254: v1(81.805,74.5) v1(108.572,74.5)
NetU5_9: U5.9 U6.14 | length 44.8
  Top Layer w0.254: v1(102.222,73) U5.9@102.222,82 ; v1(128.988,73) U6.14@128.988,82
  Bottom Layer w0.254: v1(102.222,73) v1(128.988,73)
NetU6_9: U6.9 U7.14 | length 41.8
  Top Layer w0.254: v1(122.638,74.5) U6.9@122.638,82 ; v1(149.405,74.5) U7.14@149.405,82
  Bottom Layer w0.254: v1(122.638,74.5) v1(149.405,74.5)
NetU7_9: U7.9 U8.14 | length 44.8
  Top Layer w0.254: v1(143.055,73) U7.9@143.055,82 ; v1(169.822,73) U8.14@169.822,82
  Bottom Layer w0.254: v1(143.055,73) v1(169.822,73)
NetU8_9: U8.9 U9.14 | length 41.8
  Top Layer w0.254: v1(163.472,74.5) U8.9@163.472,82 ; v1(190.238,74.5) U9.14@190.238,82
  Bottom Layer w0.254: v1(163.472,74.5) v1(190.238,74.5)
NetU9_9: U9.9 U10.14 | length 44.8
  Top Layer w0.254: v1(183.888,73) U9.9@183.888,82 ; v1(210.655,73) U10.14@210.655,82
  Bottom Layer w0.254: v1(183.888,73) v1(210.655,73)
NetU10_9: U10.9 U11.14 | length 41.8
  Top Layer w0.254: v1(204.305,74.5) U10.9@204.305,82 ; v1(231.072,74.5) U11.14@231.072,82
  Bottom Layer w0.254: v1(204.305,74.5) v1(231.072,74.5)
NetU11_9: U11.9 U12.14 | length 44.8
  Top Layer w0.254: v1(224.722,73) U11.9@224.722,82 ; v1(251.488,73) U12.14@251.488,82
  Bottom Layer w0.254: v1(224.722,73) v1(251.488,73)
NetU12_9: U12.9 U13.14 | length 41.8
  Top Layer w0.254: v1(245.138,74.5) U12.9@245.138,82 ; v1(271.905,74.5) U13.14@271.905,82
  Bottom Layer w0.254: v1(245.138,74.5) v1(271.905,74.5)
PA0: U14.10
PA1: U14.11
PA2: U14.12
PA3: U14.13
PA6: U14.16
PA8: U14.29
PA11: C25.1 R111.2 SW1.2 U14.32 | length 43.4
  Top Layer w0.254: U14.32@33.075,109.75 42.52,109.75 47.27,105 58.658,105 R111.2@60.5,106.842 ; C25.1@60.5,110.158 62.96,110.158 63.268,109.85 SW1.2@65.75,109.85 SW1.2@70.25,109.85
  Top Layer w0.508: R111.2@60.5,106.842 C25.1@60.5,110.158
PA12: C26.1 R112.2 SW2.2 U14.33 | length 28
  Top Layer w0.254: U14.33@33.075,110.25 43.8,110.25 44.21,109.84 47.74,109.84 SW2.2@47.75,109.85 SW2.2@52.25,109.85 54.731,109.85 55.04,110.158 C26.1@57.5,110.158
  Top Layer w0.508: R112.2@57.5,106.842 C26.1@57.5,110.158
PA15: U14.38
PB0: U14.18
PB1: U14.19
PB3: U14.39
PB4: U14.40
PB5: U14.41
PB6: U14.42
PB7: U14.43
PB8: U14.45
PB9: U14.46
PB10: U14.21
PB11: U14.22
PB12: U14.25
PB13: U14.26
PB14: U14.27
PB15: U14.28
PC13: U14.2
RX: PROGRAM.5 U14.31 | length 46.7
  Top Layer w0.254: U14.31@33.075,109.25 35.8,109.25 38,107.05 v1(38,105)
  Bottom Layer w0.254: PROGRAM.5@1.49,108.35 3.32,108.35 4.39,109.42 13.12,109.42 16.27,106.27 36.73,106.27 v1(38,105)
SWCLK: PROGRAM.1 U14.37 | length 35.2
  Top Layer w0.254: U14.37@31.75,113.075 v1(33.075,113.075)
  Bottom Layer w0.254: PROGRAM.1@1.49,118.51 19.34,118.51 22.36,115.49 30.66,115.49 v1(33.075,113.075)
SWDIO: PROGRAM.2 U14.34 | length 35.5
  Top Layer w0.254: v1(30.5,110) 31.25,110.75 U14.34@33.075,110.75
  Bottom Layer w0.254: PROGRAM.2@1.49,115.97 4.14,115.97 5.46,117.29 14.91,117.29 17.73,114.47 26.03,114.47 v1(30.5,110)
TX: PROGRAM.6 U14.30 | length 40.8
  Top Layer w0.254: U14.30@33.075,108.75 34.83,108.75 36,107.58 v1(36,105)
  Bottom Layer w0.254: PROGRAM.6@1.49,105.81 3.25,105.81 4.06,105 v1(36,105)
VBAT: CoinCell.2 U14.1 | length 61.9
  Top Layer w0.254: v1(22,113) 23.25,111.75 U14.1@24.925,111.75
  Bottom Layer w0.254: v1(22,113) 28,107 CoinCell.2@78,107
VIN: CP16.1 CP18.1 L1.2 MODULE1.2 P1.1 pad.801 pad.821 pad.822 | length 298.5
  Top Layer w0.508: L1.2@277,110.789 277,110.79 CP18.1@279.5,110.79 279.5,109.04 CP16.1@283,109.04 289,109.04 ; P1.1@289,114 289,109.04 ; pad.801@293,2.342 290.5,2.342 290.46,2.382 pad.822@290.46,58 pad.821@290.46,62 290.46,109.04 289,109.04
  Bottom Layer w0.508: MODULE1.2@136,111.75 136,104.81 289,104.81 P1.1@289,114
pads on no net: D1.0 QP1.0 SW1.0 SW2.0 U13.9 Y2.

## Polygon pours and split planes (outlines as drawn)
GND on Bottom Layer "Bottom Layer-No Net" (hatched 45Degree grid 0.508 track 0.203, remove dead copper, pour order 0): 0,0 295,0 295,120 0,120 0,0

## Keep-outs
Keep-Out Layer:
  the board outline again, w0.254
